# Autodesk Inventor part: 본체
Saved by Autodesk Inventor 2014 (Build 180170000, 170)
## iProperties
Created: 2026-06
Part Number: 본체
Material: 알루미늄 6061
Document SubType Name: Modeling
Designer: dg
Density: 2.71 g/cm^3
Appearance: 알루미늄 - 평지
Mass: 525.704 g
Surface Area: 617.461 cm^2
Volume: 193.987 cm^3
Author: jhkim
Creation Date: 2026-05-29
Sending System: Autodesk Inventor 2027
Preprocessor: ST-DEVELOPER v20.1
Author: dg
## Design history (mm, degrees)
node "본체1"
node "솔리드1"
node "기준1"
